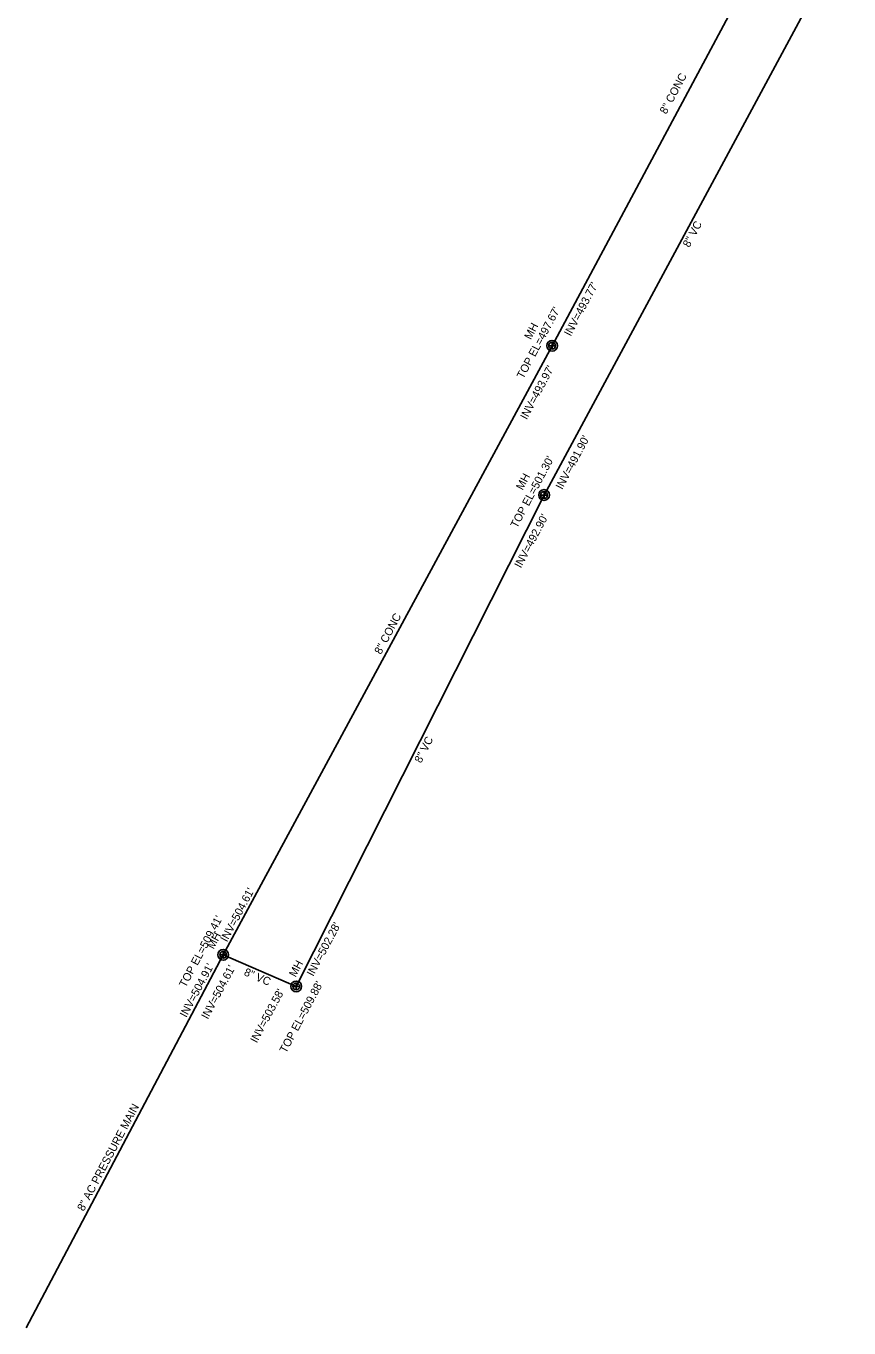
# Model space of a CAD drawing. Extents: x 1975698 to 1978521, y 778259 to 782969.
# Drawn here: x 1975698 to 1976109, y 778259 to 778910 of the extents above; entities that cross this region are included whole.
import ezdxf

# ---------------------------------------------------------------- set-up
doc = ezdxf.new("R2010")
doc.units = 0
for name, color, linetype in [('Old_Level_11', 7, 'Continuous'), ('Prop Horizontal Alignment', 7, 'Continuous'), ('Prop Horizontal Alignment Station Label', 7, 'Continuous'), ('Prop Horizontal Alignment Tick Large', 7, 'Continuous'), ('Prop WCC CELL', 7, 'Continuous')]:
    doc.layers.add(name, color=color, linetype=linetype)

# ---------------------------------------------------------------- blocks, each defined once
blk = doc.blocks.new('EXIST UTILITIES SANITARY SEWER MANHOLE')
at = {"layer": 'Prop Horizontal Alignment'}
blk.add_lwpolyline([(0, 0.034), (0, -0.034), (0, 0), (0.034, 0), (-0.034, 0)], dxfattribs=at)
for radius in [0.0539, 0.0342]:
    blk.add_circle((0, 0), radius, dxfattribs=at)

msp = doc.modelspace()

# ---------------------------------------------------------------- linework, layer by layer
at = {"layer": 'Prop Horizontal Alignment Station Label'}
for p, q in [((1975960.52, 778749.94), (1976101.41, 779013.48)), ((1975956.48, 778675.34), (1976108.88, 778958.11)), ((1975796.09, 778445.57), (1975960.52, 778749.94)), ((1975832.59, 778429.76), (1975956.48, 778675.34)), ((1975796.09, 778445.57), (1975697.55, 778259.09)), ((1975796.09, 778445.57), (1975832.59, 778429.76))]:
    msp.add_line(p, q, dxfattribs=at)

# ---------------------------------------------------------------- block references
at = {"layer": 'Prop Horizontal Alignment', "xscale": 50, "yscale": 50}
for p in [(1975960.52, 778749.94), (1975956.48, 778675.34), (1975796.09, 778445.57), (1975832.59, 778429.76)]:
    msp.add_blockref('EXIST UTILITIES SANITARY SEWER MANHOLE', p, dxfattribs=at)

# ---------------------------------------------------------------- texts
at = {"layer": 'Old_Level_11'}
for s, rotation, p in [('8" CONC', 61.87066, (1976017.54, 778865.36)), ('8" VC', 61.87066, (1976029.07, 778798.76)), ('8" CONC', 62.14881, (1975874.93, 778595.37)), ('8" VC', 63.23034, (1975895.01, 778541.08)), ('8" VC', 336.5722, (1975806.15, 778435.49))]:
    msp.add_text(s, height=4, rotation=rotation, dxfattribs=at).set_placement(p)
at = {"layer": 'Prop Horizontal Alignment Tick Large'}
msp.add_text('8" AC PRESSURE MAIN', height=4, rotation=62.14881, dxfattribs=at).set_placement((1975726.39, 778317.14))
at = {"layer": 'Prop WCC CELL'}
for s, p in [("INV=493.77'", (1975969.76, 778754.38)), ("TOP EL=497.67'", (1975946.1, 778733.07)), ('MH', (1975949.85, 778752.66)), ("INV=493.97'", (1975947.81, 778712.71)), ("INV=491.90'", (1975965.54, 778677.76)), ("TOP EL=501.30'", (1975942.94, 778658.5)), ('MH', (1975945.73, 778677.48)), ("INV=492.90'", (1975944.89, 778638.51)), ("INV=504.61'", (1975797.96, 778451.66)), ("TOP EL=509.41'", (1975777.34, 778428.9)), ("INV=502.28'", (1975841.11, 778434.48)), ('MH', (1975791.32, 778448.1)), ("INV=504.91'", (1975777.67, 778413.94)), ("INV=504.61'", (1975788.43, 778413.05)), ('MH', (1975832.27, 778434.11)), ("INV=503.58'", (1975812.91, 778401.18)), ("TOP EL=509.88'", (1975827.52, 778396.11))]:
    msp.add_text(s, height=4, rotation=61.91412, dxfattribs=at).set_placement(p)

doc.saveas('drawing.dxf')
